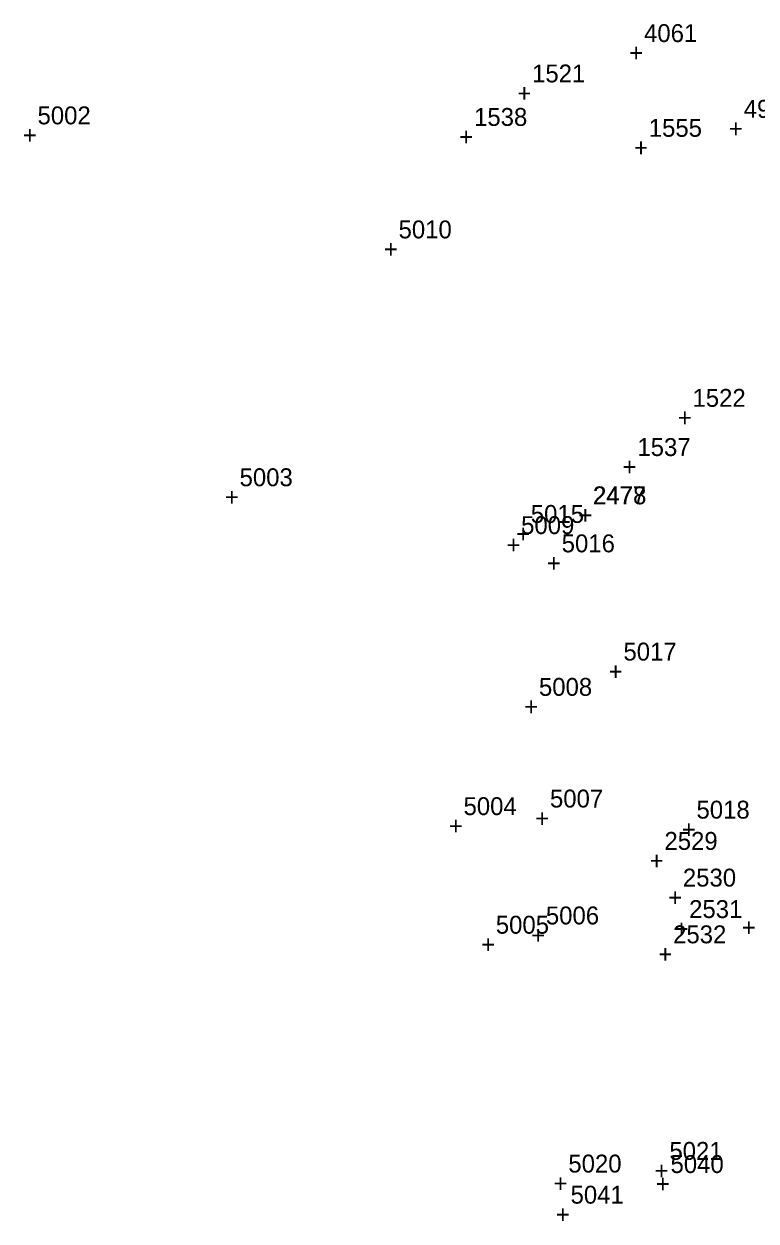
# Model space of a CAD drawing. Extents: x 1036751 to 1042192, y 772604 to 785439.
# Drawn here: x 1038698.2 to 1038800.5, y 778019.6 to 778186.9 of the extents above; entities that cross this region are included whole.
import ezdxf

# ---------------------------------------------------------------- set-up
doc = ezdxf.new("R2010")
doc.units = 0
for name, color, linetype in [('S_Drainage_Culvert_Top', 7, 'Continuous'), ('S_Drainage_Invert', 7, 'Continuous'), ('S_Ground_Elevation', 7, 'Continuous'), ('S_RetWall_Top', 7, 'Continuous'), ('S_Roadway_Centerline', 7, 'Continuous'), ('S_Roadway_Edge_Pavement', 7, 'Continuous'), ('S_Utilities_UG_Water_Line', 7, 'Continuous')]:
    doc.layers.add(name, color=color, linetype=linetype)

msp = doc.modelspace()

# ---------------------------------------------------------------- texts
at = {"layer": 'S_Drainage_Culvert_Top'}
for s, p in [('2478', (1038777.75, 778119.74)), ('+', (1038775.69, 778116.99))]:
    msp.add_text(s, height=2.5, dxfattribs=at).set_placement(p)
at = {"layer": 'S_Drainage_Invert'}
for s, p in [('2477', (1038777.7, 778119.74)), ('+', (1038775.64, 778116.99))]:
    msp.add_text(s, height=2.5, dxfattribs=at).set_placement(p)
at = {"layer": 'S_Ground_Elevation'}
for s, p in [('5002', (1038700.09, 778172.85)), ('4992', (1038798.79, 778173.76)), ('+', (1038698.03, 778170.1)), ('+', (1038796.73, 778171.01)), ('5010', (1038750.55, 778156.91)), ('+', (1038748.49, 778154.16)), ('5003', (1038728.33, 778122.27)), ('+', (1038726.27, 778119.52)), ('5015', (1038769.03, 778117.14)), ('5009', (1038767.68, 778115.58)), ('+', (1038766.97, 778114.39)), ('5016', (1038773.35, 778113.03)), ('+', (1038765.62, 778112.83)), ('+', (1038771.28, 778110.28)), ('5017', (1038781.98, 778097.9)), ('+', (1038779.92, 778095.15)), ('5008', (1038770.17, 778092.97)), ('+', (1038768.11, 778090.22)), ('5004', (1038759.63, 778076.3)), ('5007', (1038771.71, 778077.36)), ('5018', (1038792.19, 778075.81)), ('+', (1038769.65, 778074.61)), ('+', (1038757.57, 778073.55)), ('+', (1038790.13, 778073.06)), ('5006', (1038771.14, 778061.02)), ('5005', (1038764.14, 778059.72)), ('+', (1038769.08, 778058.27)), ('+', (1038798.52, 778059.35)), ('+', (1038762.08, 778056.97)), ('5021', (1038788.4, 778028.11)), ('5020', (1038774.28, 778026.34)), ('5040', (1038788.56, 778026.27)), ('+', (1038786.34, 778025.36)), ('+', (1038772.22, 778023.59)), ('+', (1038786.5, 778023.52)), ('5041', (1038774.59, 778021.99)), ('+', (1038772.53, 778019.24))]:
    msp.add_text(s, height=2.5, dxfattribs=at).set_placement(p)
at = {"layer": 'S_RetWall_Top'}
for s, p in [('2529', (1038787.71, 778071.44)), ('+', (1038785.65, 778068.69)), ('2530', (1038790.29, 778066.31)), ('+', (1038788.23, 778063.56)), ('2531', (1038791.16, 778061.91)), ('2532', (1038788.92, 778058.38)), ('+', (1038789.1, 778059.16)), ('+', (1038786.86, 778055.63))]:
    msp.add_text(s, height=2.5, dxfattribs=at).set_placement(p)
at = {"layer": 'S_Roadway_Centerline'}
for s, p in [('1521', (1038769.21, 778178.71)), ('+', (1038767.15, 778175.96)), ('1522', (1038791.63, 778133.37)), ('+', (1038789.57, 778130.62))]:
    msp.add_text(s, height=2.5, dxfattribs=at).set_placement(p)
at = {"layer": 'S_Roadway_Edge_Pavement'}
for s, p in [('1538', (1038761.1, 778172.63)), ('+', (1038759.04, 778169.88)), ('1555', (1038785.52, 778171.11)), ('+', (1038783.46, 778168.36)), ('1537', (1038783.93, 778126.49)), ('+', (1038781.87, 778123.74))]:
    msp.add_text(s, height=2.5, dxfattribs=at).set_placement(p)
at = {"layer": 'S_Utilities_UG_Water_Line'}
for s, p in [('4061', (1038784.86, 778184.35)), ('+', (1038782.8, 778181.6))]:
    msp.add_text(s, height=2.5, dxfattribs=at).set_placement(p)

doc.saveas('drawing.dxf')
